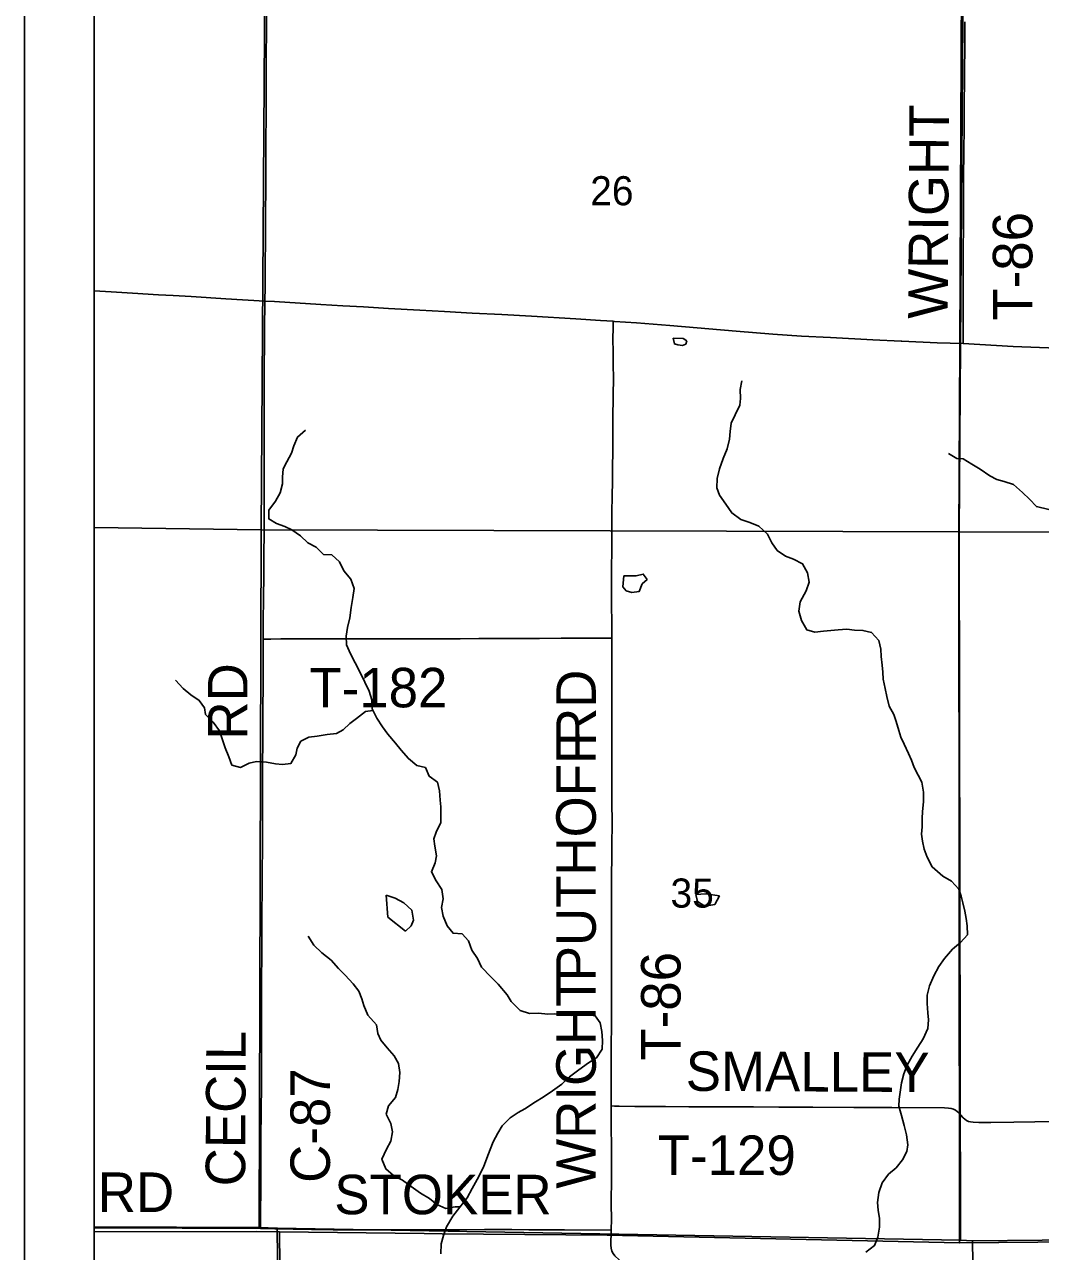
# Model space of a CAD drawing. Extents: x 0 to 1391, y -24 to 440.
# Drawn here: x 340 to 369.21, y 328.34 to 363.63 of the extents above; entities that cross this region are included whole.
import ezdxf

# ---------------------------------------------------------------- set-up
doc = ezdxf.new("R2010")
doc.units = 0
for name, color, linetype in [('GM_X_County_Road', 7, 'Continuous'), ('GM_X_County_Road_Text', 7, 'Continuous'), ('GM_X_Minor_Lake', 7, 'Continuous'), ('GM_X_Minor_River', 7, 'Continuous'), ('GM_X_Section', 7, 'Continuous'), ('GM_X_Section_Text', 7, 'Continuous'), ('GM_X_State_Route', 7, 'Continuous'), ('GM_X_Township', 7, 'Continuous'), ('GM_X_Township_Road', 7, 'Continuous'), ('GM_X_Township_Road_Text', 7, 'Continuous'), ('SH_Data', 7, 'Continuous')]:
    doc.layers.add(name, color=color, linetype=linetype)

msp = doc.modelspace()

# ---------------------------------------------------------------- linework, layer by layer
at = {"layer": 'GM_X_County_Road'}
for points in [[(346.911, 355.676), (346.918, 356.088), (346.918, 356.274), (346.919, 356.747), (346.925, 357.417), (346.924, 357.865), (346.932, 358.436), (346.934, 358.685), (346.938, 359.207), (346.94, 359.803), (346.94, 360.387), (346.945, 360.909), (346.948, 361.493), (346.949, 362.052), (346.951, 362.835), (346.954, 363.332), (346.955, 364.351)], [(346.862, 345.952), (346.862, 346.415), (346.872, 347.174), (346.876, 347.745), (346.885, 348.267), (346.887, 349.123), (346.886, 349.928), (346.887, 350.214), (346.89, 350.673), (346.89, 351.071), (346.889, 351.805), (346.889, 352.55), (346.891, 352.961), (346.893, 353.842), (346.896, 354.377), (346.902, 355.011), (346.909, 355.52), (346.911, 355.676)], [(346.783, 328.997), (346.789, 329.489), (346.796, 330.086), (346.795, 330.682), (346.794, 331.092), (346.797, 331.602), (346.81, 333.143), (346.814, 333.59), (346.812, 334.46), (346.811, 334.87), (346.814, 335.442), (346.817, 336.113), (346.822, 336.896), (346.826, 338.027), (346.833, 338.785), (346.834, 339.245), (346.838, 339.978), (346.841, 340.687), (346.844, 341.296), (346.845, 341.855), (346.846, 342.29), (346.852, 343.048), (346.856, 343.818), (346.857, 344.75), (346.862, 345.657), (346.862, 345.952)], [(342, 329.023), (342.086, 329.023), (342.807, 329.018), (343.13, 329.018), (343.813, 329.019), (344.533, 329.013), (345.565, 329.014), (346.149, 329.011), (346.783, 328.997)]]:
    msp.add_lwpolyline(points, dxfattribs=at)
at = {"layer": 'GM_X_Minor_Lake'}
for p, q in [((359.018, 354.434), (359.039, 354.535)), ((357.236, 347.77), (357.199, 347.457)), ((357.199, 347.457), (357.297, 347.345))]:
    msp.add_line(p, q, dxfattribs=at)
for points in [[(358.651, 354.612), (358.685, 354.441), (358.783, 354.416), (358.919, 354.398), (359.018, 354.434)], [(359.039, 354.535), (358.938, 354.595), (358.651, 354.612)], [(357.297, 347.345), (357.463, 347.297), (357.675, 347.323), (357.763, 347.541), (357.902, 347.668), (357.791, 347.822), (357.586, 347.773), (357.236, 347.77)], [(350.398, 338.584), (350.45, 337.957), (350.951, 337.554)], [(350.951, 337.554), (351.112, 337.709), (351.183, 337.867), (351.136, 338.156), (350.905, 338.366), (350.657, 338.499), (350.398, 338.584)], [(359.981, 338.566), (359.592, 338.631), (359.3, 338.603)], [(359.3, 338.603), (359.353, 338.408), (359.563, 338.275), (359.844, 338.315), (359.981, 338.566)]]:
    msp.add_lwpolyline(points, dxfattribs=at)
at = {"layer": 'GM_X_Minor_River'}
for points in [[(361.114, 349.205), (360.859, 349.302), (360.595, 349.392), (360.335, 349.58), (360.166, 349.835), (359.983, 350.097), (359.905, 350.304), (359.911, 350.569), (359.978, 350.849), (360.091, 351.15), (360.204, 351.428), (360.271, 351.7), (360.292, 351.927), (360.32, 352.162), (360.432, 352.402), (360.567, 352.68), (360.587, 352.877), (360.578, 353.135), (360.629, 353.377)], [(351.845, 339.72), (351.799, 340.002), (351.766, 340.208), (351.839, 340.404), (351.967, 340.674), (351.973, 340.94), (351.97, 341.129), (351.952, 341.32), (351.935, 341.586), (351.873, 341.838), (351.635, 342.01), (351.527, 342.263), (351.278, 342.322), (351.04, 342.517), (350.826, 342.758), (350.664, 342.959), (350.443, 343.222), (350.297, 343.43), (350.128, 343.677), (349.991, 343.946), (349.982, 344.204), (349.912, 344.456), (349.782, 344.718), (349.63, 345.032), (349.507, 345.27), (349.376, 345.532), (349.261, 345.785), (349.252, 346.035), (349.288, 346.285), (349.356, 346.564), (349.393, 346.86), (349.438, 347.147), (349.474, 347.404), (349.382, 347.672), (349.183, 347.92), (349.06, 348.173), (348.838, 348.376), (348.595, 348.389), (348.381, 348.599), (348.141, 348.718), (347.934, 348.92), (347.688, 349.093), (347.485, 349.189), (347.245, 349.278), (347.021, 349.412), (347.026, 349.663), (347.214, 349.916), (347.349, 350.164), (347.416, 350.42), (347.413, 350.61), (347.434, 350.853), (347.537, 351.055), (347.672, 351.303), (347.745, 351.514), (347.849, 351.762), (348.081, 351.961)], [(367.96, 350.543), (367.757, 350.645), (367.48, 350.84), (367.239, 350.98), (366.991, 351.136), (366.802, 351.147), (366.569, 351.288)], [(369.456, 349.676), (369.093, 349.765), (368.892, 349.973), (368.69, 350.174), (368.436, 350.399), (368.172, 350.487), (367.96, 350.543)], [(364.193, 328.319), (364.44, 328.51), (364.537, 328.751), (364.581, 329.038), (364.58, 329.289), (364.548, 329.532), (364.522, 329.746), (364.567, 330.033), (364.657, 330.312), (364.845, 330.565), (365.062, 330.75), (365.249, 330.973), (365.369, 331.213), (365.396, 331.41), (365.358, 331.699), (365.288, 331.967), (365.212, 332.249), (365.142, 332.517), (365.147, 332.721), (365.175, 332.926), (365.211, 333.191), (365.278, 333.447), (365.383, 333.703), (365.525, 333.957), (365.683, 334.219), (365.84, 334.458), (365.969, 334.751), (365.99, 335.001), (365.972, 335.199), (365.956, 335.473), (365.954, 335.708), (366.021, 335.98), (366.141, 336.265), (366.292, 336.535), (366.449, 336.767), (366.683, 337.034), (366.915, 337.226), (367.117, 337.449), (367.108, 337.708), (367.075, 337.921), (367.035, 338.127), (366.98, 338.363), (366.932, 338.562), (366.868, 338.761), (366.654, 338.986), (366.407, 339.136), (366.095, 339.401), (365.958, 339.678), (365.872, 339.915), (365.817, 340.137), (365.792, 340.342), (365.812, 340.554), (365.81, 340.797), (365.822, 340.994), (365.844, 341.275), (365.851, 341.555), (365.805, 341.837), (365.696, 342.037), (365.58, 342.26), (365.501, 342.474), (365.415, 342.666), (365.292, 342.927), (365.199, 343.134), (365.143, 343.325), (365.066, 343.585), (364.995, 343.784), (364.864, 344.023), (364.795, 344.305), (364.747, 344.534), (364.693, 344.801), (364.675, 344.999), (364.657, 345.204), (364.633, 345.455), (364.622, 345.661), (364.56, 345.913), (364.354, 346.145), (364.105, 346.204), (363.862, 346.21), (363.643, 346.238), (363.393, 346.221), (363.18, 346.196), (362.975, 346.178), (362.724, 346.153), (362.491, 346.219), (362.338, 346.489), (362.261, 346.756), (362.305, 347.021), (362.472, 347.343), (362.561, 347.592), (362.515, 347.859), (362.369, 348.12), (362.107, 348.248), (361.882, 348.337), (361.643, 348.502), (361.489, 348.718), (361.358, 348.971), (361.114, 349.205)], [(350.014, 343.899), (349.807, 343.867), (349.544, 343.668), (349.351, 343.521), (349.158, 343.343), (348.966, 343.241), (348.7, 343.209), (348.418, 343.163), (348.175, 343.13), (347.945, 343.014), (347.841, 342.819), (347.799, 342.623), (347.657, 342.375), (347.413, 342.343), (347.217, 342.363), (346.953, 342.414), (346.672, 342.429), (346.459, 342.38), (346.214, 342.264), (345.965, 342.331), (345.872, 342.568), (345.773, 342.829), (345.68, 343.081), (345.61, 343.318), (345.419, 343.566), (345.204, 343.783), (345.178, 343.973), (345.024, 344.19), (344.778, 344.347), (344.563, 344.534), (344.341, 344.775)], [(351.966, 328.272), (351.98, 328.56), (352.047, 328.801), (352.128, 329.05), (352.318, 329.357), (352.513, 329.618), (352.724, 329.878), (352.875, 330.148), (353.01, 330.411), (353.193, 330.763), (353.29, 331.026), (353.387, 331.275), (353.475, 331.493), (353.61, 331.74), (353.729, 331.95), (353.962, 332.187), (354.193, 332.334), (354.385, 332.443), (354.693, 332.641), (354.916, 332.78), (355.185, 332.956), (355.448, 333.154), (355.673, 333.362), (355.935, 333.56), (356.213, 333.766), (356.444, 333.913), (356.609, 334.159), (356.622, 334.41), (356.598, 334.668), (356.551, 334.912), (356.404, 335.121), (356.163, 335.157), (355.95, 335.139), (355.722, 335.129), (355.488, 335.157), (355.238, 335.171), (355.049, 335.167), (354.777, 335.197), (354.518, 335.18), (354.248, 335.27), (353.996, 335.526), (353.88, 335.726), (353.622, 336.028), (353.407, 336.238), (353.141, 336.518), (353.025, 336.763), (352.857, 337.01), (352.765, 337.27), (352.587, 337.472), (352.323, 337.493), (352.153, 337.709), (352.039, 337.985), (351.992, 338.229), (352.036, 338.486), (351.997, 338.753), (351.836, 339), (351.698, 339.261), (351.81, 339.516), (351.845, 339.72)], [(352.519, 329.625), (352.385, 329.621), (352.111, 329.574), (351.856, 329.694), (351.648, 329.865), (351.386, 330.016), (351.118, 330.204), (350.864, 330.392), (350.61, 330.527), (350.387, 330.714), (350.273, 330.998), (350.408, 331.283), (350.535, 331.508), (350.579, 331.78), (350.532, 332.024), (350.394, 332.285), (350.461, 332.527), (350.663, 332.765), (350.73, 332.999), (350.773, 333.233), (350.794, 333.483), (350.748, 333.75), (350.632, 333.965), (350.425, 334.197), (350.241, 334.414), (350.162, 334.613), (350.122, 334.857), (349.871, 335.136), (349.757, 335.412), (349.701, 335.611), (349.615, 335.825), (349.446, 336.042), (349.217, 336.29), (349.024, 336.476), (348.818, 336.717), (348.55, 336.928), (348.32, 337.145), (348.152, 337.407)]]:
    msp.add_lwpolyline(points, dxfattribs=at)
at = {"layer": 'GM_X_Section'}
for p, q in [((342, 369.141), (342, 349.165)), ((342, 349.165), (342, 329.048)), ((342, 329.048), (342, 309.239))]:
    msp.add_line(p, q, dxfattribs=at)
for points in [[(342, 349.165), (346.805, 349.092), (346.942, 369.105), (342, 369.141)], [(342, 329.048), (346.743, 329.025), (346.805, 349.092), (342, 349.165)], [(342, 309.239), (347.482, 309.199), (347.266, 329.014), (346.743, 329.025), (342, 329.048)]]:
    msp.add_lwpolyline(points, dxfattribs=at)
for points in [[(367.019, 369.133), (366.873, 349.037), (346.805, 349.092), (346.942, 369.105)], [(387.261, 369.12), (387.273, 348.998), (366.873, 349.037), (367.019, 369.133)], [(346.805, 349.092), (366.873, 349.037), (366.91, 328.665), (347.266, 329.014), (346.743, 329.025)], [(366.873, 349.037), (387.273, 348.998), (387.293, 328.839), (367.258, 328.65), (366.91, 328.665)], [(366.91, 328.665), (367.258, 328.65), (367.565, 308.841), (347.482, 309.199), (347.266, 329.014)], [(387.293, 328.839), (387.556, 309.121), (387.563, 308.758), (367.565, 308.841), (367.258, 328.65)]]:
    msp.add_lwpolyline(points, close=True, dxfattribs=at)
at = {"layer": 'GM_X_State_Route'}
for points in [[(342, 355.971), (342.487, 355.942), (343.108, 355.905), (343.852, 355.857), (344.278, 355.832)], [(344.278, 355.832), (344.795, 355.803), (345.787, 355.74), (346.911, 355.676), (347.189, 355.66), (348.517, 355.577), (349.149, 355.539), (349.745, 355.507), (350.464, 355.463), (351.37, 355.41), (352.078, 355.379), (352.872, 355.329), (353.728, 355.287), (354.572, 355.239), (355.85, 355.164), (356.565, 355.117)], [(356.565, 355.117), (356.925, 355.094), (356.966, 355.091), (357.599, 355.049), (358.553, 354.976), (360.459, 354.808), (361.512, 354.724), (362.343, 354.67), (363.174, 354.624), (364.391, 354.563), (365.21, 354.524)], [(365.21, 354.524), (365.222, 354.524), (366.241, 354.478), (366.99, 354.453), (368.426, 354.373), (369.692, 354.318)]]:
    msp.add_lwpolyline(points, dxfattribs=at)
at = {"layer": 'GM_X_Township'}
msp.add_line((342, 409.484), (342, 328.905), dxfattribs=at)
for points in [[(342, 328.905), (346.676, 328.912), (347.332, 328.904), (351.489, 328.852), (352.004, 328.845), (356.749, 328.811), (366.886, 328.586), (366.882, 332.104), (366.863, 348.93), (366.895, 354.384), (366.961, 368.979), (367.052, 379.006), (367.112, 389.089), (367.16, 409.322), (346.96, 409.447), (342, 409.484)], [(366.961, 368.979), (366.895, 354.384), (366.863, 348.93), (366.886, 328.586), (407.375, 328.93), (427.17, 329.098), (437.196, 329.183), (447.101, 329.514), (447.1, 329.807), (447.095, 330.76), (447.22, 339.546), (447.212, 344.406), (447.181, 349.555), (447.172, 350.472), (447.169, 351.314), (447.12, 358.688), (447.049, 369.139)], [(347.795, 282), (347.727, 288.944), (347.628, 298.991), (347.529, 308.991), (347.435, 318.551), (347.332, 328.904), (346.676, 328.912), (342, 328.905)], [(342, 328.905), (342, 282), (347.795, 282)], [(427.17, 329.098), (407.375, 328.93), (377.029, 328.672), (366.886, 328.586), (356.749, 328.811), (352.004, 328.845), (351.489, 328.852), (347.332, 328.904), (347.435, 318.551), (347.529, 308.991), (347.628, 298.991), (347.727, 288.944), (347.795, 282)]]:
    msp.add_lwpolyline(points, dxfattribs=at)
at = {"layer": 'GM_X_Township_Road'}
for points in [[(366.99, 354.453), (366.985, 355.057), (366.985, 356.784), (366.989, 357.169), (366.994, 357.803), (366.996, 358.238), (366.997, 358.461), (367, 358.995), (367.003, 359.318), (367.009, 359.877), (367.018, 360.76), (367.022, 361.182), (367.026, 362.189), (367.037, 363.083), (367.04, 363.456), (367.041, 363.705)], [(356.887, 345.976), (356.886, 346.117), (356.886, 346.403), (356.88, 346.962), (356.878, 347.41), (356.881, 347.894), (356.887, 348.602), (356.891, 348.987), (356.89, 349.273), (356.89, 349.633), (356.894, 350.031), (356.902, 350.527), (356.906, 350.775), (356.914, 351.471), (356.917, 352.043), (356.919, 352.465), (356.924, 352.776), (356.928, 353.111), (356.93, 353.31), (356.931, 353.434), (356.929, 353.856), (356.929, 354.216), (356.92, 354.576), (356.923, 354.912), (356.925, 355.094)], [(346.862, 345.952), (346.945, 345.952), (347.081, 345.953), (347.367, 345.959), (347.74, 345.963), (348.212, 345.959), (348.746, 345.958), (349.056, 345.959), (349.466, 345.958), (349.864, 345.957), (350.311, 345.961), (350.684, 345.964), (351.069, 345.96), (351.342, 345.959), (352.076, 345.958), (352.523, 345.961), (353.058, 345.97), (353.431, 345.97), (353.629, 345.969), (353.716, 345.97), (354.089, 345.971), (354.387, 345.974), (354.81, 345.974), (355.431, 345.978), (356.887, 345.976)], [(356.869, 332.526), (356.869, 332.812), (356.869, 333.085), (356.868, 333.619), (356.869, 333.905), (356.87, 334.091), (356.876, 335.01), (356.879, 335.495), (356.876, 335.979), (356.875, 336.104), (356.874, 336.402), (356.874, 336.749), (356.878, 337.085), (356.88, 337.607), (356.88, 338.228), (356.881, 338.75), (356.881, 339.147), (356.885, 339.694), (356.889, 340.129), (356.893, 340.551), (356.893, 340.762), (356.89, 341.172), (356.89, 341.533), (356.887, 342.092), (356.888, 342.626), (356.889, 343.11), (356.891, 343.657), (356.888, 344.303), (356.888, 344.713), (356.888, 345.148), (356.888, 345.508), (356.887, 345.976)], [(356.872, 328.956), (356.875, 329.283), (356.871, 329.693), (356.875, 330.5), (356.878, 331.408), (356.872, 331.867), (356.869, 332.165), (356.869, 332.526)], [(356.869, 332.526), (356.963, 332.523), (357.1, 332.518), (357.547, 332.513), (357.907, 332.509), (358.429, 332.506), (359.1, 332.503), (359.734, 332.498), (360.38, 332.5), (360.964, 332.498), (361.685, 332.492), (361.983, 332.491), (362.666, 332.486), (363.847, 332.484), (364.605, 332.481), (364.94, 332.48), (366.455, 332.47), (366.567, 332.466), (366.64, 332.453), (366.711, 332.429), (366.765, 332.4), (366.816, 332.364), (366.862, 332.323), (366.981, 332.194)], [(366.981, 332.194), (366.989, 332.185), (367.035, 332.144), (367.086, 332.109), (367.141, 332.082), (367.201, 332.064), (367.275, 332.055), (367.437, 332.053), (367.784, 332.054), (368.443, 332.059), (369.052, 332.066), (369.623, 332.075)], [(346.783, 328.997), (347.193, 328.993)], [(347.193, 328.993), (348.249, 328.976), (348.871, 328.965), (349.231, 328.962), (349.417, 328.96), (349.827, 328.96), (349.963, 328.96), (350.249, 328.961), (350.585, 328.963), (351.205, 328.962), (351.466, 328.961), (351.864, 328.96), (352.323, 328.96), (352.51, 328.961), (353.23, 328.969), (354.013, 328.969), (354.497, 328.966), (355.069, 328.962), (355.528, 328.96), (356.872, 328.956)], [(356.872, 328.956), (356.861, 328.521), (356.868, 328.436), (356.887, 328.353), (356.923, 328.277), (356.976, 328.211), (357.094, 328.103), (357.148, 328.05), (357.187, 328), (357.214, 327.957), (357.239, 327.898), (357.253, 327.836), (357.258, 327.789)]]:
    msp.add_lwpolyline(points, dxfattribs=at)
at = {"layer": 'SH_Data'}
for p, q in [((340, 420), (340, 280)), ((342, 418), (342, 282))]:
    msp.add_line(p, q, dxfattribs=at)

# ---------------------------------------------------------------- texts
at = {"layer": 'GM_X_County_Road_Text'}
for s, rotation, p in [('RD', 90, (346.41, 343.063)), ('CECIL', 89.7636, (346.343, 330.211)), ('C-87', 90, (348.782, 330.313)), ('RD', 0, (342.107, 329.476))]:
    msp.add_text(s, height=1.1364, rotation=rotation, dxfattribs=at).set_placement(p)
at = {"layer": 'GM_X_Section_Text'}
for s, p in [('26', (356.265, 358.43)), ('35', (358.574, 338.23))]:
    msp.add_text(s, height=0.8371, rotation=0, dxfattribs=at).set_placement(p)
at = {"layer": 'GM_X_Township_Road_Text'}
for s, rotation, p in [('WRIGHT', 89.6575, (366.543, 355.163)), ('T-86', 90, (368.979, 355.113)), ('T-182', 0, (348.19, 343.99)), ('RD', 90, (356.427, 342.879)), ('PUTHOFF', 90, (356.426, 336.113)), ('T-86', 90, (358.863, 333.829)), ('WRIGHT', 90, (356.426, 330.146)), ('SMALLEY', 359.7086, (359.01, 332.96)), ('T-129', 0, (358.207, 330.54)), ('STOKER', 0, (348.907, 329.41))]:
    msp.add_text(s, height=1.1364, rotation=rotation, dxfattribs=at).set_placement(p)

doc.saveas('drawing.dxf')
